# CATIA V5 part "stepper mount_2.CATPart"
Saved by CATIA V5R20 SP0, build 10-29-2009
Part number: stepper mount 2
Source: Unknown
Bounding box of the stored display mesh (mm): x 0 to 45, y 0 to 48.3, z -61 to 42.3
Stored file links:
  C:\Users\Ikarus\OneDrive - FH JOANNEUM\BAC - Arbeit 1\CAD Modell\CAD-Modell-Step files\stepper mount\stepper mount_2.CATPart
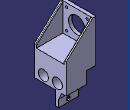
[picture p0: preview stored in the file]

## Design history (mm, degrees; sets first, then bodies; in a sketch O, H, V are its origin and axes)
Body1 (main body)
  Solid1 "Hauptkörper": solid without history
